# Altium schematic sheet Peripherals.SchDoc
size A4; Revision: B.2
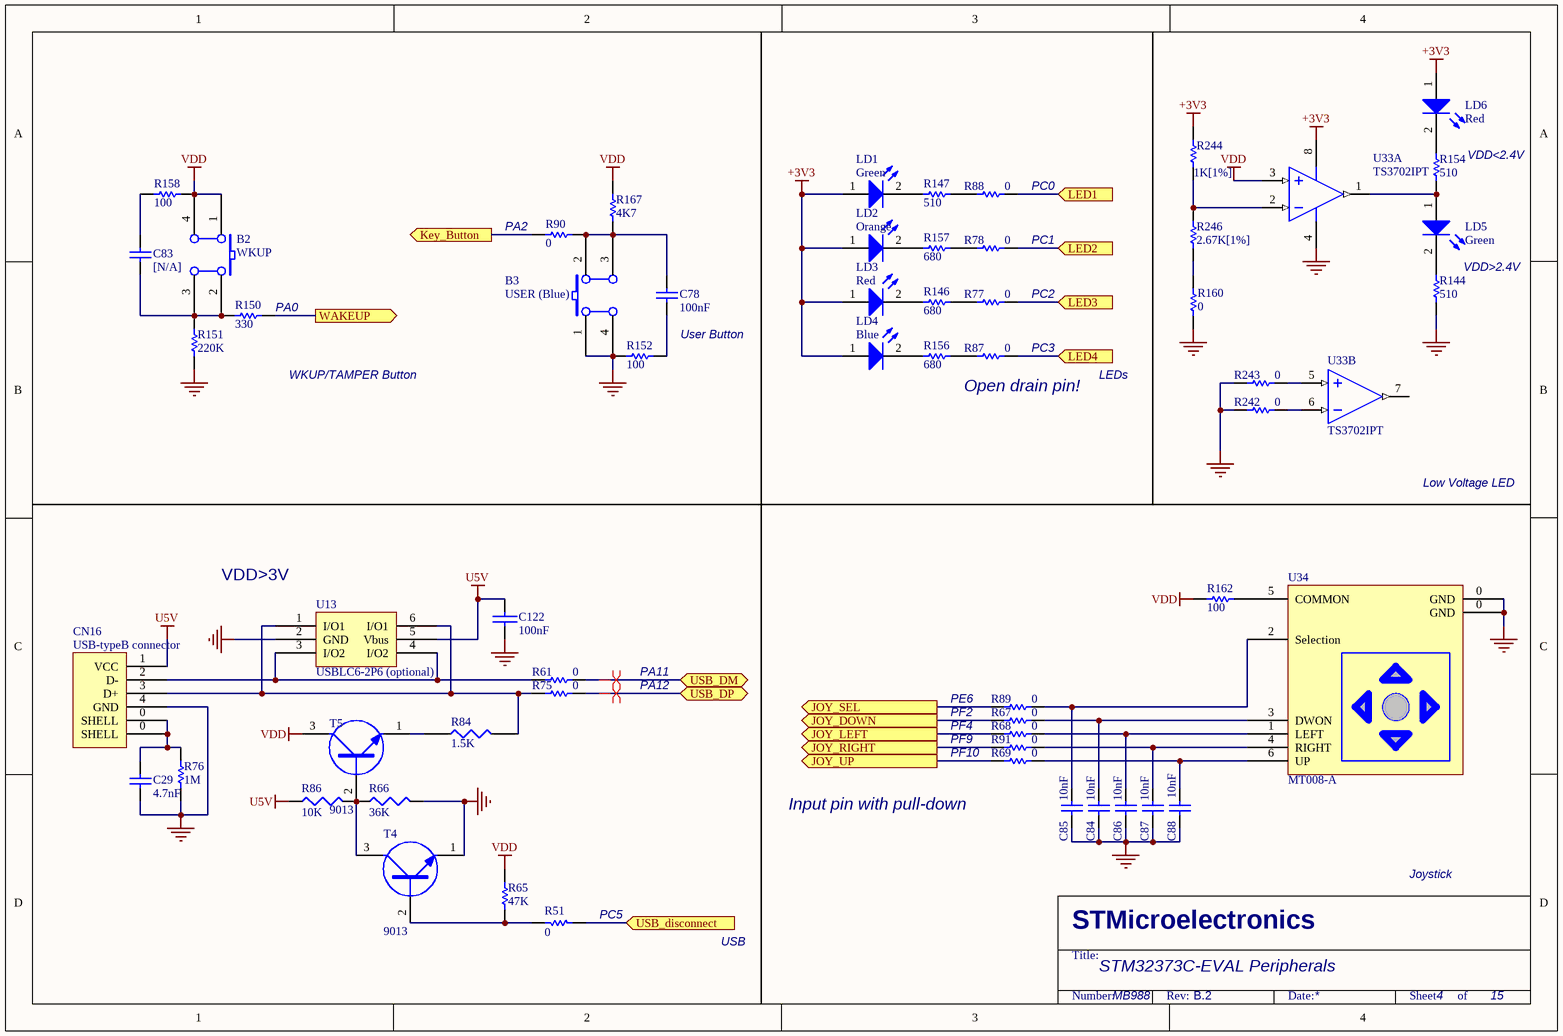
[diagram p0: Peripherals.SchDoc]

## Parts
B2  WKUP  [PB10]
B3  USER (Blue)  [PB10]
C29  4.7nF  [0603C]
C78  100nF  [0603C]
C83  [N/A]  [0603C]
C84  10nF  [0603C]
C85  10nF  [0603C]
C86  10nF  [0603C]
C87  10nF  [0603C]
C88  10nF  [0603C]
C122  100nF  [0603C]
CN16  USB-typeB connector  [USB-B]
LD1  Green  [0603D]
LD2  Orange  [0603D]
LD3  Red  [0603D]
LD4  Blue  [0603D]
LD5  Green  [0603D]
LD6  Red  [0603D]
R51  0  [0603R]
R61  0  [0603R]
R65  47K  [0603R]
R66  36K  [0603R]
R67  0  [0603R]
R68  0  [0603R]
R69  0  [0603R]
R75  0  [0603R]
R76  1M  [0603R]
R77  0  [0603R]
R78  0  [0603R]
R84  1.5K  [0603R]
R86  10K  [0603R]
R87  0  [0603R]
R88  0  [0603R]
R89  0  [0603R]
R90  0  [0603R]
R91  0  [0603R]
R144  510  [0603R]
R146  680  [0603R]
R147  510  [0603R]
R150  330  [0603R]
R151  220K  [0603R]
R152  100  [0603R]
R154  510  [0603R]
R156  680  [0603R]
R157  680  [0603R]
R158  100  [0603R]
R160  0  [0603R]
R162  100  [0603R]
R167  4K7  [0603R]
R242  0  [0603R]
R243  0  [0603R]
R244  1K[1%]  [0603R]
R246  2.67K[1%]  [0603R]
T4  9013  [SOT-23]
T5  9013  [SOT-23]
U13  USBLC6-2P6 (optional)  [SOT-666]
U33  TS3702IPT  [TSSOP8(6.4)]  (parts A,B of 2)
U34  MT008-A  [JOY]

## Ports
JOY_DOWN (out), JOY_LEFT (out), JOY_RIGHT (out), JOY_SEL (out), JOY_UP (out), Key_Button (out), LED1 (in), LED2 (in), LED3 (in), LED4 (in), USB_disconnect (in), USB_DM (bidir), USB_DP (bidir), WAKEUP (out)

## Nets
+3V3: LD1.1(A) LD2.1(A) LD3.1(A) LD4.1(A) LD6.1(A) R244.2 U33.8(V+)
GND: B3.1(A0) B3.4(A1) C29.1 C84.1 C85.1 C86.1 C87.1 C88.1 C122.2 CN16.4(GND) R66.2 R76.1 R144.2 R151.2 R152.1 R160.2 R242.2 R243.2 T4.1(E) U13.2(GND) U33.4(V-) U34.0(GND)
U5V: C122.1 CN16.1(VCC) R86.1 U13.5(Vbus)
VDD: B2.1(A0) B2.4(A1) R65.2 R158.1 R162.1 R167.2 T5.3(C) U33.3(IN+)
JOY_DOWN: R67.2 ; port JOY_DOWN
JOY_LEFT: R68.2 ; port JOY_LEFT
JOY_RIGHT: R91.2 ; port JOY_RIGHT
JOY_SEL: R89.2 ; port JOY_SEL
JOY_UP: R69.2 ; port JOY_UP
Key_Button: R90.2 ; port Key_Button
LED1: R88.1 ; port LED1
LED2: R78.1 ; port LED2
LED3: R77.1 ; port LED3
LED4: R87.1 ; port LED4
USB_disconnect: R51.2 ; port USB_disconnect
USB_DM: R61.1 ; port USB_DM
USB_DP: R75.1 ; port USB_DP
WAKEUP: R150.2 ; port WAKEUP
NetB2_2: B2.2(B0) B2.3(B1) C83.2 R150.1 R151.1
NetB3_2: B3.2(B0) B3.3(B1) C78.2 R90.1 R167.1
NetC29_2: C29.2 CN16.0(SHELL) R76.2
NetC78_1: C78.1 R152.2
NetC83_1: C83.1 R158.2
NetC84_2: C84.2 R67.1 U34.3(DWON)
NetC85_2: C85.2 R89.1 U34.2(Selection)
NetC86_2: C86.2 R68.1 U34.1(LEFT)
NetC87_2: C87.2 R91.1 U34.4(RIGHT)
NetC88_2: C88.2 R69.1 U34.6(UP)
NetCN16_2: CN16.2(D-) R61.2 U13.3(I/O2) U13.4(I/O2)
NetCN16_3: CN16.3(D+) R75.2 R84.2 U13.1(I/O1) U13.6(I/O1)
NetLD1_2: LD1.2(K) R147.2
NetLD2_2: LD2.2(K) R157.2
NetLD3_2: LD3.2(K) R146.2
NetLD4_2: LD4.2(K) R156.2
NetLD5_1: LD5.1(A) R154.2 U33.1(OUT)
NetLD5_2: LD5.2(K) R144.1
NetLD6_2: LD6.2(K) R154.1
NetR51_1: R51.1 R65.1 T4.2(B)
NetR66_1: R66.1 R86.2 T4.3(C) T5.2(B)
NetR77_2: R77.2 R146.1
NetR78_2: R78.2 R157.1
NetR84_1: R84.1 T5.1(E)
NetR87_2: R87.2 R156.1
NetR88_2: R88.2 R147.1
NetR160_1: R160.1 R246.1
NetR162_2: R162.2 U34.5(COMMON)
NetR242_1: R242.1 U33.6(IN-)
NetR243_1: R243.1 U33.5(IN+)
NetR244_1: R244.1 R246.2 U33.2(IN-)

Not connected (* = marked no-connect by the designer): U33 7(OUT)

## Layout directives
differential pair: USB_DM, USB_DP

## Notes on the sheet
- VDD<2.4V
- (near R90) PA2
- (near R88) PC0
- (near R78) PC1
- (near R150) PA0
- (near R77) PC2
- VDD>2.4V
- WKUP/TAMPER Button
- User Button
- (near R87) PC3
- LEDs
- Open drain pin!
- Low Voltage LED
- VDD>3V
- PA12
- PA11
- PF2
- PE6
- PF10
- PF9
- PF4
- Input pin with pull-down
- (near R51) PC5
- Joystick
- USB
- STM32373C-EVAL Peripherals
- MB988
- 4
- 15

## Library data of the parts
B2 B3 = SW PUSHBUTTON: SE PUSHBUTTON
C29 C78 C83-C88 = CAP: Capacitor; Value: 100pF
C122 = CAP: Capacitor
CN16 = USB-B
LD1-LD6 = LED2: Typical RED, GREEN, YELLOW, AMBER GaAs LED
R51 R61 R65 R67-R69 R75-R78 R87-R91 R144 R146 R147 R150 R152 R154 R156-R158 R160 R162 R242-R244 R246 = Res1: Resistor; Value: 1K
R66 R86 = R: Right: 20; Bottom: 30
R84 = RES1
R151 R167 = res1: Resistor; Value: 1K
T4 T5 = NPN
U13 = USBLC6-2
U33 = LM393PT
U34 = MT-008A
